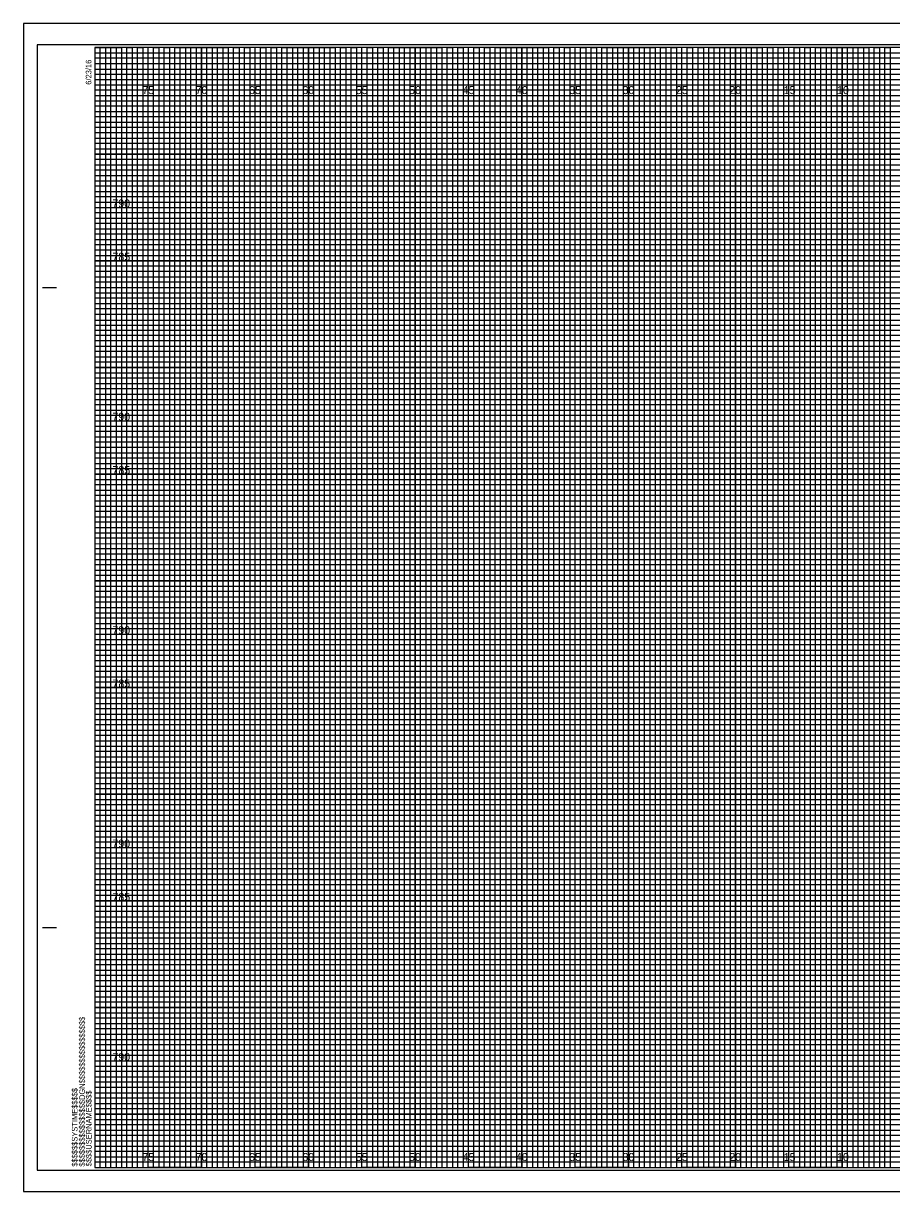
# Model space of a CAD drawing. Extents: x -7 to 162, y 108 to 217.
# Drawn here: x -6.7 to 74.6, y 107.7 to 217.2 of the extents above; entities that cross this region are included whole.
import ezdxf

# ---------------------------------------------------------------- set-up
doc = ezdxf.new("R2010")
doc.units = 0
for name, color, linetype in [('Exist Cross Section Cell', 7, 'Continuous'), ('Exist XS Center Line Elevation Label', 7, 'Continuous'), ('Prop CMT Pvmt Course 2 Wedge', 7, 'Continuous'), ('Prop CMT Pvmt Surface Shoulder', 7, 'Continuous'), ('Prop CMT Shld Paved Course 1', 7, 'Continuous'), ('Prop CMT Shld Paved Course 3', 7, 'Continuous'), ('Prop XS Elevation Labels', 7, 'Continuous'), ('Prop XS Hydro Elevations', 7, 'Continuous'), ('Prop XS SE Text', 7, 'Continuous'), ('Prop XS Side Slope Text', 7, 'Continuous'), ('Sheet Cutting Line CELL', 7, 'Continuous')]:
    doc.layers.add(name, color=color, linetype=linetype)

msp = doc.modelspace()

# ---------------------------------------------------------------- linework, layer by layer
at = {"layer": 'Exist Cross Section Cell'}
for p, q in [((5, 215), (0, 215)), ((5, 110), (5, 215)), ((15, 215), (10, 215)), ((10, 215), (10, 110)), ((15, 110), (15, 215)), ((25, 215), (20, 215)), ((20, 215), (20, 110)), ((25, 110), (25, 215)), ((35, 215), (30, 215)), ((30, 215), (30, 110)), ((35, 110), (35, 215)), ((45, 215), (40, 215)), ((40, 215), (40, 110)), ((45, 110), (45, 215)), ((55, 215), (50, 215)), ((50, 215), (50, 110)), ((55, 110), (55, 215)), ((65, 215), (60, 215)), ((60, 215), (60, 110)), ((65, 110), (65, 215)), ((75, 215), (70, 215)), ((70, 215), (70, 110)), ((10, 110), (5, 110)), ((20, 110), (15, 110)), ((30, 110), (25, 110)), ((40, 110), (35, 110)), ((50, 110), (45, 110)), ((60, 110), (55, 110)), ((70, 110), (65, 110))]:
    msp.add_line(p, q, dxfattribs=at)
for points in [[(0, 210), (160, 210), (160, 205), (0, 205)], [(0, 200), (160, 200), (160, 195), (0, 195)], [(0, 190), (160, 190), (160, 185), (0, 185)], [(0, 180), (160, 180), (160, 175), (0, 175)], [(0, 170), (160, 170), (160, 165), (0, 165)], [(0, 160), (160, 160), (160, 155), (0, 155)], [(0, 150), (160, 150), (160, 145), (0, 145)], [(0, 140), (160, 140), (160, 135), (0, 135)], [(0, 130), (160, 130), (160, 125), (0, 125)], [(0, 120), (160, 120), (160, 115), (0, 115)]]:
    msp.add_lwpolyline(points, dxfattribs=at)
at = {"layer": 'Exist XS Center Line Elevation Label'}
for points in [[(0, 215), (2.5, 215), (2.5, 110), (7.5, 110), (7.5, 215), (12.5, 215), (12.5, 110), (17.5, 110), (17.5, 215), (22.5, 215), (22.5, 110), (27.5, 110), (27.5, 215), (32.5, 215), (32.5, 110), (37.5, 110), (37.5, 215), (42.5, 215), (42.5, 110), (47.5, 110), (47.5, 215), (52.5, 215), (52.5, 110), (57.5, 110), (57.5, 215), (62.5, 215), (62.5, 110), (67.5, 110), (67.5, 215), (72.5, 215), (72.5, 110), (77.5, 110)], [(0, 212.5), (137.5, 212.5)], [(0, 202.5), (160, 202.5), (160, 207.5), (0, 207.5)], [(0, 192.5), (160, 192.5), (160, 197.5), (0, 197.5)], [(0, 182.5), (160, 182.5), (160, 187.5), (0, 187.5)], [(0, 172.5), (160, 172.5), (160, 177.5), (0, 177.5)], [(0, 162.5), (160, 162.5), (160, 167.5), (0, 167.5)], [(0, 152.5), (160, 152.5), (160, 157.5), (0, 157.5)], [(0, 142.5), (160, 142.5), (160, 147.5), (0, 147.5)], [(0, 132.5), (160, 132.5), (160, 137.5), (0, 137.5)], [(0, 122.5), (160, 122.5), (160, 127.5), (0, 127.5)], [(0, 112.5), (160, 112.5), (160, 117.5), (0, 117.5)]]:
    msp.add_lwpolyline(points, dxfattribs=at)
at = {"layer": 'Prop CMT Pvmt Course 2 Wedge'}
for p, q in [((5, 110), (5, 215)), ((10, 110), (10, 215)), ((15, 110), (15, 215)), ((20, 110), (20, 215)), ((25, 110), (25, 215)), ((30, 110), (30, 215)), ((35, 110), (35, 215)), ((40, 110), (40, 215)), ((45, 110), (45, 215)), ((50, 110), (50, 215)), ((55, 110), (55, 215)), ((60, 110), (60, 215)), ((65, 110), (65, 215)), ((70, 110), (70, 215)), ((0, 210), (160, 210)), ((0, 205), (160, 205)), ((0, 200), (160, 200)), ((0, 195), (160, 195)), ((0, 190), (160, 190)), ((0, 185), (160, 185)), ((0, 180), (160, 180)), ((0, 175), (160, 175)), ((0, 170), (160, 170)), ((0, 165), (160, 165)), ((0, 160), (160, 160)), ((0, 155), (160, 155)), ((0, 150), (160, 150)), ((0, 145), (160, 145)), ((0, 140), (160, 140)), ((0, 135), (160, 135)), ((0, 130), (160, 130)), ((0, 125), (160, 125)), ((0, 120), (160, 120)), ((0, 115), (160, 115))]:
    msp.add_line(p, q, dxfattribs=at)
at = {"layer": 'Prop CMT Pvmt Surface Shoulder'}
msp.add_lwpolyline([(-5.4, 109.75), (161.2, 109.75), (161.2, 215.25), (-5.4, 215.25)], close=True, dxfattribs=at)
at = {"layer": 'Prop CMT Shld Paved Course 1'}
for points in [[(0, 110), (0.5, 110), (0.5, 215), (1, 215), (1, 110)], [(1, 110), (1.5, 110), (1.5, 215), (2, 215), (2, 110)], [(2.5, 110), (3, 110), (3, 215), (3.5, 215), (3.5, 110)], [(3.5, 110), (4, 110), (4, 215), (4.5, 215), (4.5, 110)], [(5, 110), (5.5, 110), (5.5, 215), (6, 215), (6, 110)], [(6, 110), (6.5, 110), (6.5, 215), (7, 215), (7, 110)], [(7.5, 110), (8, 110), (8, 215), (8.5, 215), (8.5, 110)], [(8.5, 110), (9, 110), (9, 215), (9.5, 215), (9.5, 110)], [(10, 110), (10.5, 110), (10.5, 215), (11, 215), (11, 110)], [(11, 110), (11.5, 110), (11.5, 215), (12, 215), (12, 110)], [(12.5, 110), (13, 110), (13, 215), (13.5, 215), (13.5, 110)], [(13.5, 110), (14, 110), (14, 215), (14.5, 215), (14.5, 110)], [(15, 110), (15.5, 110), (15.5, 215), (16, 215), (16, 110)], [(16, 110), (16.5, 110), (16.5, 215), (17, 215), (17, 110)], [(17.5, 110), (18, 110), (18, 215), (18.5, 215), (18.5, 110)], [(18.5, 110), (19, 110), (19, 215), (19.5, 215), (19.5, 110)], [(20, 110), (20.5, 110), (20.5, 215), (21, 215), (21, 110)], [(21, 110), (21.5, 110), (21.5, 215), (22, 215), (22, 110)], [(22.5, 110), (23, 110), (23, 215), (23.5, 215), (23.5, 110)], [(23.5, 110), (24, 110), (24, 215), (24.5, 215), (24.5, 110)], [(25, 110), (25.5, 110), (25.5, 215), (26, 215), (26, 110)], [(26, 110), (26.5, 110), (26.5, 215), (27, 215), (27, 110)], [(27.5, 110), (28, 110), (28, 215), (28.5, 215), (28.5, 110)], [(28.5, 110), (29, 110), (29, 215), (29.5, 215), (29.5, 110)], [(30, 110), (30.5, 110), (30.5, 215), (31, 215), (31, 110)], [(31, 110), (31.5, 110), (31.5, 215), (32, 215), (32, 110)], [(32.5, 110), (33, 110), (33, 215), (33.5, 215), (33.5, 110)], [(33.5, 110), (34, 110), (34, 215), (34.5, 215), (34.5, 110)], [(35, 110), (35.5, 110), (35.5, 215), (36, 215), (36, 110)], [(36, 110), (36.5, 110), (36.5, 215), (37, 215), (37, 110)], [(37.5, 110), (38, 110), (38, 215), (38.5, 215), (38.5, 110)], [(38.5, 110), (39, 110), (39, 215), (39.5, 215), (39.5, 110)], [(40, 110), (40.5, 110), (40.5, 215), (41, 215), (41, 110)], [(41, 110), (41.5, 110), (41.5, 215), (42, 215), (42, 110)], [(42.5, 110), (43, 110), (43, 215), (43.5, 215), (43.5, 110)], [(43.5, 110), (44, 110), (44, 215), (44.5, 215), (44.5, 110)], [(45, 110), (45.5, 110), (45.5, 215), (46, 215), (46, 110)], [(46, 110), (46.5, 110), (46.5, 215), (47, 215), (47, 110)], [(47.5, 110), (48, 110), (48, 215), (48.5, 215), (48.5, 110)], [(48.5, 110), (49, 110), (49, 215), (49.5, 215), (49.5, 110)], [(50, 110), (50.5, 110), (50.5, 215), (51, 215), (51, 110)], [(51, 110), (51.5, 110), (51.5, 215), (52, 215), (52, 110)], [(52.5, 110), (53, 110), (53, 215), (53.5, 215), (53.5, 110)], [(53.5, 110), (54, 110), (54, 215), (54.5, 215), (54.5, 110)], [(55, 110), (55.5, 110), (55.5, 215), (56, 215), (56, 110)], [(56, 110), (56.5, 110), (56.5, 215), (57, 215), (57, 110)], [(57.5, 110), (58, 110), (58, 215), (58.5, 215), (58.5, 110)], [(58.5, 110), (59, 110), (59, 215), (59.5, 215), (59.5, 110)], [(60, 110), (60.5, 110), (60.5, 215), (61, 215), (61, 110)], [(61, 110), (61.5, 110), (61.5, 215), (62, 215), (62, 110)], [(62.5, 110), (63, 110), (63, 215), (63.5, 215), (63.5, 110)], [(63.5, 110), (64, 110), (64, 215), (64.5, 215), (64.5, 110)], [(65, 110), (65.5, 110), (65.5, 215), (66, 215), (66, 110)], [(66, 110), (66.5, 110), (66.5, 215), (67, 215), (67, 110)], [(67.5, 110), (68, 110), (68, 215), (68.5, 215), (68.5, 110)], [(68.5, 110), (69, 110), (69, 215), (69.5, 215), (69.5, 110)], [(70, 110), (70.5, 110), (70.5, 215), (71, 215), (71, 110)], [(71, 110), (71.5, 110), (71.5, 215), (72, 215), (72, 110)], [(72.5, 110), (73, 110), (73, 215), (73.5, 215), (73.5, 110)], [(73.5, 110), (74, 110), (74, 215), (74.5, 215), (74.5, 110)]]:
    msp.add_lwpolyline(points, dxfattribs=at)
at = {"layer": 'Prop CMT Shld Paved Course 3'}
msp.add_lwpolyline([(-6.7, 107.75), (161.65, 107.75), (161.65, 217.25), (-6.7, 217.25)], close=True, dxfattribs=at)
at = {"layer": 'Prop XS Hydro Elevations'}
for p, q in [((-4.9, 192.5), (-3.65, 192.5)), ((-4.85, 192.5), (-3.6, 192.5)), ((-4.9, 132.5), (-3.65, 132.5)), ((-4.85, 132.5), (-3.6, 132.5)), ((0, 110), (0, 110)), ((0, 110), (0, 110)), ((0, 110), (0, 110)), ((0, 110), (0, 110)), ((0, 110), (0, 110)), ((0, 110), (0, 110)), ((0, 110), (0, 110))]:
    msp.add_line(p, q, dxfattribs=at)
msp.add_lwpolyline([(160, 215), (0, 215), (0, 110), (160, 110)], close=True, dxfattribs=at)
at = {"layer": 'Prop XS Side Slope Text'}
for p, q in [((0, 214.5), (130, 214.5)), ((130, 213.99), (0, 213.99)), ((0, 213.99), (0, 213.5)), ((0, 213.5), (130, 213.5)), ((130, 212.94), (0, 212.94)), ((0, 212.94), (0, 212)), ((0, 212), (160, 212))]:
    msp.add_line(p, q, dxfattribs=at)
for points in [[(0, 211.5), (135, 211.5), (160, 211.5), (160, 211), (0, 211)], [(0, 210.5), (160, 210.5), (160, 209.5), (0, 209.5)], [(0, 209), (160, 209), (160, 208.5), (0, 208.49)], [(0, 208), (160, 208), (160, 207), (0, 207)], [(0, 206.5), (160, 206.5), (160, 206), (0, 206)], [(0, 205.5), (160, 205.5), (160, 204.5), (0, 204.5)], [(0, 204), (160, 204), (160, 203.5), (0, 203.5)], [(0, 203), (160, 203), (160, 202), (0, 202)], [(0, 201.5), (160, 201.5), (160, 201), (0, 201)], [(0, 200.5), (160, 200.5), (160, 199.5), (0, 199.5)], [(0, 199), (160, 199), (160, 198.5), (0, 198.5)], [(0, 198), (160, 198), (160, 196.97), (160, 196.5), (160, 196), (0, 196)], [(0, 197), (160, 197), (160, 196.5), (0, 196.5)], [(0, 195.5), (160, 195.5), (160, 194.5), (0, 194.52)], [(0, 194.52), (160, 194.5), (160, 194), (0, 194)], [(0, 193.5), (160, 193.5), (160, 193), (0, 193)], [(0, 192), (160, 192), (160, 191.5), (0, 191.5)], [(0, 191), (160, 191), (160, 190.5), (0, 190.5)], [(-0.04, 189.44), (160, 189.44), (160, 188.94), (-0.04, 188.94)], [(0, 188.5), (160, 188.5), (160, 188), (0, 188)], [(0, 187), (160, 187), (160, 186.5), (0, 186.5)], [(0, 186), (160, 186), (160, 185.5), (0, 185.5)], [(0, 184.5), (160, 184.5), (160, 184), (0, 184)], [(0, 183.5), (160, 183.5), (160, 183), (0, 183)], [(0, 182), (160, 182), (160, 181.5), (0, 181.5)], [(0, 181), (160, 181), (160, 180.5), (0, 180.5)], [(0, 179.5), (160, 179.5), (160, 178.99), (0, 179)], [(0, 178.5), (160, 178.5), (160, 178), (0, 178)], [(0, 177), (160, 177), (160, 176.5), (0, 176.5)], [(0, 176), (160, 176), (160, 175.5), (0, 175.5)], [(0, 174.5), (160, 174.5), (160, 174), (0, 174)], [(0, 173.5), (160, 173.5), (160, 173), (0, 173)], [(0, 172), (160, 172), (160, 171.5), (0, 171.5)], [(0, 171), (160, 171), (160, 170.5), (0, 170.5)], [(0, 169.5), (160, 169.5), (160, 169), (0, 169)], [(0, 168.5), (160.03, 168.46), (160, 168), (0, 168)], [(0, 167), (160, 167), (160, 166.5), (0, 166.5)], [(0, 166), (160, 166), (160, 165.5), (0, 165.5)], [(0, 164.5), (160, 164.5), (160, 164), (0, 164)], [(0, 163.5), (160, 163.5), (160, 163), (0, 163)], [(0, 162), (160, 162), (160, 161.5), (0, 161.5)], [(0, 161), (160, 161), (160, 160.5), (0, 160.5)], [(0, 159.5), (160, 159.5), (160, 159), (0, 159)], [(0, 158.5), (160, 158.5), (160, 158), (0, 158)], [(0, 157), (160, 157), (160, 156.5), (0, 156.5)], [(0, 156), (160, 156), (160, 155.5), (0, 155.5)], [(0, 154.5), (160, 154.5), (160, 154), (0, 154)], [(0, 153.5), (160, 153.5), (160, 153), (0, 153)], [(0, 152), (160, 152), (160, 151.5), (0, 151.5)], [(0, 151), (160, 151), (160, 150.5), (0, 150.5)], [(0, 149.5), (160, 149.5), (160, 148.99), (0, 149)], [(0, 148.5), (160, 148.5), (160, 148), (0, 148)], [(0, 147), (160, 147), (160, 146.5), (0, 146.5)], [(0, 146), (160, 146), (160, 145.5), (0, 145.5)], [(0, 144.5), (160, 144.5), (160, 144), (0, 144)], [(0, 143.5), (160, 143.5), (160, 143), (0, 143)], [(0, 142), (160, 142), (160, 141.5), (0, 141.5)], [(0, 141), (160, 141), (160, 140.5), (0, 140.5)], [(0, 139.5), (160, 139.5), (160, 139), (0, 139)], [(0, 138.5), (160.03, 138.46), (160, 138), (0, 138)], [(0, 137), (160, 137), (160, 136.5), (0, 136.5)], [(0, 136), (160, 136), (160, 135.5), (0, 135.5)], [(0, 134.5), (160, 134.5), (160, 134), (0, 134)], [(0, 133.5), (160, 133.5), (160, 133), (0, 133)], [(0, 132), (160, 132), (160, 131.5), (0, 131.5)], [(0, 131), (160, 131), (160, 130.5), (0, 130.5)], [(0, 129.5), (160, 129.5), (160, 129), (0, 129)], [(0, 128.5), (160, 128.5), (160, 128), (0, 128)], [(0, 127), (160, 127), (160, 126.5), (0, 126.5)], [(0, 126), (160, 126), (160, 125.5), (0, 125.5)], [(0, 124.5), (160, 124.5), (160, 124), (0, 124)], [(0, 123.5), (160, 123.5), (160, 123), (0, 123)], [(0, 122), (160, 122), (160, 121.5), (0, 121.5)], [(0, 121), (160, 121), (160, 120.5), (0, 120.5)], [(0, 119.5), (160, 119.5), (160, 119), (0, 119)], [(0, 118.5), (160, 118.5), (160, 118), (0, 118)], [(0, 117), (160, 117), (160, 116.5), (0, 116.5)], [(0, 116), (160, 116), (160, 115.5), (0, 115.5)], [(0, 114.5), (160, 114.5), (160, 114), (0, 114)], [(0, 113.5), (160, 113.5), (160, 113), (0, 113)], [(0, 112), (160, 112), (160, 111.5), (0, 111.5)], [(0, 111), (160, 111), (160, 110.5), (0, 110.5)]]:
    msp.add_lwpolyline(points, dxfattribs=at)
at = {"layer": 'Sheet Cutting Line CELL'}
for p, q in [((161.65, 217.25), (-6.7, 217.25)), ((-6.7, 217.25), (-6.7, 107.75)), ((-6.7, 107.75), (161.65, 107.75))]:
    msp.add_line(p, q, dxfattribs=at)

# ---------------------------------------------------------------- texts
at = {"layer": 'Prop XS Elevation Labels'}
for s, p in [('790', (1.63, 200)), ('785', (1.64, 195)), ('790', (1.63, 180)), ('785', (1.64, 175)), ('790', (1.63, 160)), ('785', (1.64, 155)), ('790', (1.63, 140)), ('785', (1.64, 135)), ('790', (1.63, 120))]:
    msp.add_text(s, height=0.75, dxfattribs=at).set_placement(p)
at = {"layer": 'Prop XS Hydro Elevations'}
for s, p in [('6/23/16', (-0.33, 211.5)), ('$$$$$$$$$$$$$$$$DGN$$$$$$$$$$$$$$$$', (-0.94, 110.09)), ('$$$$$$SYSTIME$$$$$', (-1.63, 110.09)), ('$$$$USERNAME$$$$', (-0.31, 110.12))]:
    msp.add_text(s, height=0.525, rotation=90, dxfattribs=at).set_placement(p)
at = {"layer": 'Prop XS SE Text'}
for s, p in [('75', (4.44, 210.62)), ('70', (9.43, 210.62)), ('65', (14.44, 210.62)), ('60', (19.43, 210.62)), ('55', (24.44, 210.62)), ('50', (29.43, 210.62)), ('45', (34.44, 210.62)), ('40', (39.43, 210.62)), ('35', (44.44, 210.62)), ('30', (49.43, 210.62)), ('25', (54.44, 210.62)), ('20', (59.43, 210.62)), ('15', (64.53, 210.62)), ('10', (69.52, 210.62)), ('75', (4.44, 110.62)), ('70', (9.43, 110.62)), ('65', (14.44, 110.62)), ('60', (19.43, 110.62)), ('55', (24.44, 110.62)), ('50', (29.43, 110.62)), ('45', (34.44, 110.62)), ('40', (39.43, 110.62)), ('35', (44.44, 110.62)), ('30', (49.43, 110.62)), ('25', (54.44, 110.62)), ('20', (59.43, 110.62)), ('15', (64.53, 110.62)), ('10', (69.52, 110.62))]:
    msp.add_text(s, height=0.75, dxfattribs=at).set_placement(p)

doc.saveas('drawing.dxf')
